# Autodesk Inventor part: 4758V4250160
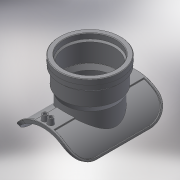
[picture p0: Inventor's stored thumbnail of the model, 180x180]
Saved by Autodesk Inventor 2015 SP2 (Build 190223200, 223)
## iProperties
Created: 2017-08
Part Number: 4758V4250160
Material: Generic
Description: PLASSON WASTEWATER SADDLE 225-250X160 PVC/PP ADAPTOR INLET
Document SubType Name: Modeling
Designer: Кирилл
Density: 1 g/cm^3
Appearance: Default
Author: Кирилл
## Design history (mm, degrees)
derived "4758V4.ipt"
feature "Solid1::4758V4.ipt"
feature "Solid2::4758V4.ipt"
feature "Solid3::4758V4.ipt"
tag "TaggingFeature1"
body "Solid1"
other parameters: "d1" = 225, "d2" = 275, "d4" = 0, "d5" = 67.5, "d6" = 8, "d7" = 30 deg, "d8" = 15 deg, "d10" = 0, "d11" = 162.5, "d38" = 1.25, "d40" = 151, "d41" = 15, "d42" = 130.5, "d43" = 17.6, "d44" = 8.8, "d46" = 5 deg, "d47" = 4, "d49" = 4, "d51" = 14, "d52" = 0, "d53" = 3, "d54" = 0, "d57" = 0.5, "d59" = 16, "d60" = 5.6, "d61" = 40 deg, "d62" = 152, "d63" = 156.8, "d64" = 144, "d65" = 155 deg, "d66" = 125, "d68" = 188.1, "d69" = 45 deg, "d70" = 175, "d72" = 7.5, "d75" = 0, "d77" = 0, "d78" = 1.6, "d81" = 37.5, "B_" = 225, "H_" = 125, "d71" = 7.5
